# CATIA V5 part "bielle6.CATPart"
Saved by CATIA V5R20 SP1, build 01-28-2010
Part number: biellebleu
Bounding box of the stored display mesh (mm): x 33 to 87, y 0 to 15, z 28.093 to 41.907
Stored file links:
  E:\EDELI\gcausse\Edeli_2012_685_gcausse\bielle6.CATPart
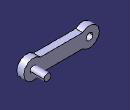
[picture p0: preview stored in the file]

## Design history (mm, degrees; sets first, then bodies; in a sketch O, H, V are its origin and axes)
Parameters
  long = 0.04
  diamtrou = 0.005
Body1 (main body)
  Sketch1 on zx-plane, origin (0, 0, 0), H (-1, 0, 0), V (0, 0, 1)
    line L1 (-44.899, 40) -> (-75.101, 40)
    line L2 (-44.899, 30) -> (-75.101, 30)
    arc A1 centre (-40, 35) radius 7 from (-44.899, 40) to (-44.899, 30) cw
    point P5 (-40, 35)
    point P6 (-35.101, 30)
    arc A2 centre (-80, 35) radius 7 from (-75.101, 40) to (-75.101, 30) ccw
    point P7 (-80, 35)
    circle A3 centre (-40, 35) radius 2.5
    distance P7 L1 = 5
    distance P5 L2 = 5
    distance L2 L1 = 10
    radius A1 = 7
    radius A2 = 7
    distance P5 P7 = 40 {= long}
    radius A3 = 2.5
    horizontal: L1 H, L2 H
    coincidence: A1 P6, P6 L2
  Pad1: profile Sketch1, direction (0, 1, 0), length 5
  Sketch2 on end face of Pad1, origin (0, 5, 0), H (-1, 0, 0), V (0, 0, 1)
    circle A1 centre (-80, 35) radius 2.5
    reference projected arc E1 centre (-80, 35) radius 7 from (-75.101, 40) to (-75.101, 30) ccw from edge [face of Pad1 from Sketch1.A2 | end face of Pad1]
    reference projected arc E2 centre (-80, 35) radius 7 from (-75.101, 40) to (-75.101, 30) ccw from edge [face of Pad1 from Sketch1.A2 | end face of Pad1]
    radius A1 = 2.5
    radius E2 = 7 (reference)
    concentricity: A1 E1
  Pad2: profile Sketch2, direction (0, 1, 0), length 10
